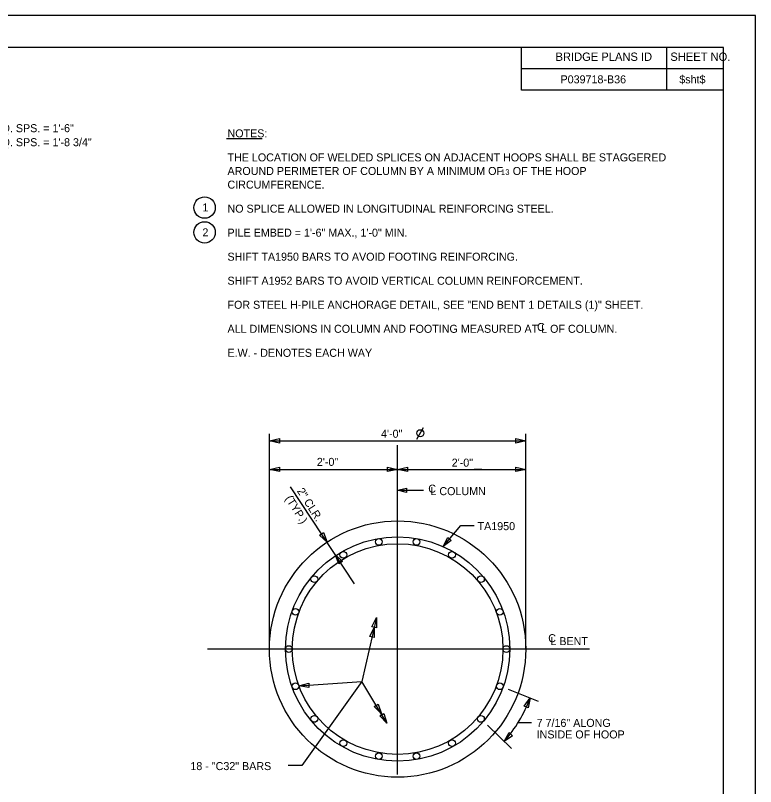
# Model space of a CAD drawing. Extents: x 1970675.2 to 1970711.3, y 796145.2 to 796167.2.
# Drawn here: x 1970699.69 to 1970711.24, y 796155.21 to 796167.25 of the extents above; entities that cross this region are included whole.
import ezdxf

# ---------------------------------------------------------------- set-up
doc = ezdxf.new("R2010")
doc.units = 0
for name, color, linetype in [('BR_AUTO DIMENSION', 7, 'Continuous'), ('BR_BORDER LINES', 7, 'Continuous'), ('BR_PRESTRESSED BEAM', 7, 'Continuous'), ('BR_REBAR', 7, 'Continuous'), ('BR_TEXT', 7, 'Continuous'), ('Default', 7, 'Continuous'), ('Level 31', 7, 'Continuous')]:
    doc.layers.add(name, color=color, linetype=linetype)

msp = doc.modelspace()

# ---------------------------------------------------------------- linework, layer by layer
at = {"layer": 'BR_AUTO DIMENSION'}
for p, q in [((1970703.651, 796157.357), (1970703.651, 796160.718)), ((1970707.651, 796159.386), (1970707.651, 796160.718)), ((1970703.651, 796160.606), (1970707.651, 796160.606)), ((1970703.651, 796160.162), (1970707.651, 796160.162)), ((1970704.98, 796158.374), (1970703.978, 796159.89)), ((1970705.651, 796159.835), (1970706.057, 796159.835)), ((1970706.36, 796158.958), (1970706.638, 796159.284)), ((1970706.638, 796159.284), (1970706.845, 796159.284)), ((1970707.651, 796157.357), (1970707.651, 796159.386)), ((1970705.32, 796157.85), (1970705.092, 796156.853)), ((1970704.109, 796156.781), (1970705.092, 796156.853)), ((1970705.092, 796156.853), (1970704.155, 796155.538)), ((1970705.485, 796156.198), (1970705.092, 796156.853)), ((1970705.485, 796156.198), (1970705.092, 796156.853)), ((1970707.377, 796156.732), (1970707.843, 796156.546)), ((1970707.051, 796156.168), (1970707.428, 796155.803)), ((1970707.741, 796156.203), (1970707.528, 796156.203)), ((1970704.155, 796155.538), (1970703.941, 796155.538))]:
    msp.add_line(p, q, dxfattribs=at)
for points in [[(1970703.807, 796160.57), (1970703.651, 796160.606), (1970703.807, 796160.642)], [(1970707.495, 796160.642), (1970707.651, 796160.606), (1970707.495, 796160.57)], [(1970703.807, 796160.126), (1970703.651, 796160.162), (1970703.807, 796160.198)], [(1970705.495, 796160.198), (1970705.651, 796160.162), (1970705.495, 796160.126)], [(1970705.807, 796160.126), (1970705.651, 796160.162), (1970705.807, 796160.198)], [(1970707.495, 796160.198), (1970707.651, 796160.162), (1970707.495, 796160.126)], [(1970705.79, 796159.803), (1970705.651, 796159.835), (1970705.79, 796159.867)], [(1970704.493, 796159.176), (1970704.549, 796159.026), (1970704.433, 796159.137)], [(1970706.488, 796159.053), (1970706.36, 796158.958), (1970706.434, 796159.1)], [(1970704.731, 796158.685), (1970704.675, 796158.835), (1970704.791, 796158.725)], [(1970705.25, 796157.706), (1970705.32, 796157.85), (1970705.32, 796157.69)], [(1970705.216, 796157.552), (1970705.286, 796157.696), (1970705.286, 796157.536)], [(1970704.267, 796156.755), (1970704.109, 796156.781), (1970704.263, 796156.827)], [(1970707.623, 796156.467), (1970707.719, 796156.595), (1970707.689, 796156.438)], [(1970705.348, 796156.496), (1970705.397, 796156.344), (1970705.286, 796156.459)], [(1970705.435, 796156.351), (1970705.484, 796156.199), (1970705.373, 796156.314)], [(1970707.446, 796156.004), (1970707.315, 796155.913), (1970707.393, 796156.053)]]:
    msp.add_lwpolyline(points, close=True, dxfattribs=at)
for centre in [(1970702.638, 796164.248), (1970702.638, 796163.86)]:
    msp.add_circle(centre, 0.167, dxfattribs=at)
msp.add_arc((1970705.651, 796157.357), 2.203, 319.0275, 339.7613, dxfattribs=at)
at = {"layer": 'BR_BORDER LINES'}
for p, q in [((1970710.736, 796166.746), (1970677.07, 796166.746)), ((1970707.584, 796166.08), (1970707.584, 796166.746)), ((1970709.85, 796166.08), (1970709.85, 796166.746)), ((1970710.736, 796145.746), (1970710.736, 796166.746)), ((1970707.584, 796166.417), (1970710.736, 796166.417)), ((1970709.85, 796166.417), (1970710.736, 796166.417)), ((1970710.736, 796166.08), (1970707.584, 796166.08))]:
    msp.add_line(p, q, dxfattribs=at)
at = {"layer": 'BR_PRESTRESSED BEAM'}
msp.add_circle((1970705.651, 796157.357), 2, dxfattribs=at)
at = {"layer": 'BR_REBAR'}
for centre, radius in [((1970705.651, 796157.357), 1.75), ((1970705.357, 796159.029), 0.0529), ((1970705.946, 796159.029), 0.0529), ((1970704.803, 796158.827), 0.0529), ((1970706.5, 796158.827), 0.0529), ((1970704.351, 796158.448), 0.0529), ((1970706.951, 796158.448), 0.0529), ((1970704.057, 796157.938), 0.0529), ((1970707.246, 796157.938), 0.0529), ((1970703.954, 796157.357), 0.0529), ((1970707.348, 796157.357), 0.0529), ((1970704.057, 796156.777), 0.0529), ((1970707.246, 796156.777), 0.0529), ((1970704.351, 796156.267), 0.0529), ((1970706.951, 796156.267), 0.0529), ((1970704.803, 796155.888), 0.0529), ((1970706.5, 796155.888), 0.0529), ((1970705.357, 796155.686), 0.0529), ((1970705.946, 796155.686), 0.0529)]:
    msp.add_circle(centre, radius, dxfattribs=at)
at = {"layer": 'BR_TEXT'}
for p, q in [((1970702.981, 796165.324), (1970703.536, 796165.324)), ((1970705.952, 796160.635), (1970706.057, 796160.817)), ((1970703.651, 796160.162), (1970703.762, 796160.162)), ((1970705.651, 796160.162), (1970705.537, 796160.162)), ((1970705.651, 796160.162), (1970705.774, 796160.162)), ((1970706.964, 796160.162), (1970706.846, 796160.162))]:
    msp.add_line(p, q, dxfattribs=at)
msp.add_circle((1970706.004, 796160.726), 0.055, dxfattribs=at)
at = {"layer": 'Default'}
for p, q in [((1970705.651, 796155.399), (1970705.651, 796160.538)), ((1970708.647, 796157.357), (1970702.682, 796157.357))]:
    msp.add_line(p, q, dxfattribs=at)
at = {"layer": 'Level 31'}
msp.add_lwpolyline([(1970675.236, 796145.246), (1970711.236, 796145.246), (1970711.236, 796167.246), (1970675.236, 796167.246)], close=True, dxfattribs=at)
msp.add_circle((1970705.651, 796157.357), 1.644, dxfattribs=at)

# ---------------------------------------------------------------- texts
at = {"layer": 'BR_TEXT'}
for s, height, p in [('BRIDGE PLANS ID', 0.13, (1970708.115, 796166.537)), ('SHEET NO.', 0.13, (1970709.906, 796166.537)), ('P039718-B36', 0.125, (1970708.193, 796166.186)), ('$sht$', 0.125, (1970710.046, 796166.186)), ('- 3 EQ. SPS. = 1\'-6"', 0.125, (1970699.118, 796165.424)), ('NOTES:', 0.125, (1970702.996, 796165.343)), ('- 3 EQ. SPS. = 1\'-8 3/4"', 0.125, (1970699.118, 796165.205)), ('THE LOCATION OF WELDED SPLICES ON ADJACENT HOOPS SHALL BE STAGGERED', 0.125, (1970702.996, 796164.968)), ('AROUND PERIMETER OF COLUMN BY A MINIMUM OF ', 0.125, (1970702.996, 796164.756)), ('1', 0.0875, (1970707.263, 796164.757)), ('3', 0.0875, (1970707.332, 796164.757)), (' OF THE HOOP', 0.125, (1970707.401, 796164.756)), ('CIRCUMFERENCE.', 0.125, (1970702.996, 796164.543)), ('1', 0.125, (1970702.605, 796164.187)), ('NO SPLICE ALLOWED IN LONGITUDINAL REINFORCING STEEL.', 0.125, (1970702.996, 796164.168)), ('2', 0.125, (1970702.605, 796163.798)), ('PILE EMBED = 1\'-6" MAX., 1\'-0" MIN.', 0.125, (1970702.996, 796163.793)), ('SHIFT TA1950 BARS TO AVOID FOOTING REINFORCING.', 0.125, (1970702.996, 796163.418)), ('SHIFT A1952 BARS TO AVOID VERTICAL COLUMN REINFORCEMENT.', 0.125, (1970702.996, 796163.043)), ('FOR STEEL H-PILE ANCHORAGE DETAIL, SEE "END BENT 1 DETAILS (1)" SHEET.', 0.125, (1970702.996, 796162.668)), ('ALL DIMENSIONS IN COLUMN AND FOOTING MEASURED AT L OF COLUMN. ', 0.125, (1970702.996, 796162.293)), ('C', 0.125, (1970707.827, 796162.321)), ('E.W. - DENOTES EACH WAY', 0.125, (1970702.996, 796161.918)), ('C', 0.125, (1970706.129, 796159.798)), ('C', 0.125, (1970708.001, 796157.464))]:
    msp.add_text(s, height=height, dxfattribs=at).set_placement(p)
for s, rotation, p in [('4\'-0" ', 360, (1970705.392, 796160.655)), ('2\'-0"', 360, (1970704.391, 796160.216)), ('2\'-0"', 360, (1970706.495, 796160.204)), ('2" CLR.', 302.3602, (1970704.075, 796159.824)), ('L COLUMN', 360, (1970706.163, 796159.759)), ('(TYP.)', 302.3602, (1970703.89, 796159.707)), ('TA1950', 360, (1970706.898, 796159.213)), ('L BENT', 360, (1970708.035, 796157.418)), ('7 7/16" ALONG', 360, (1970707.82, 796156.142)), ('INSIDE OF HOOP', 360, (1970707.82, 796155.962)), ('18 - "C32" BARS', 360, (1970702.417, 796155.468))]:
    msp.add_text(s, height=0.125, rotation=rotation, dxfattribs=at).set_placement(p)

doc.saveas('drawing.dxf')
